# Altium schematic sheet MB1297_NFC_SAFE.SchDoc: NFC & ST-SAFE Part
size A4; DocumentNumber: MB1297; Revision: C; SheetNumber: 7; SheetTotal: 11
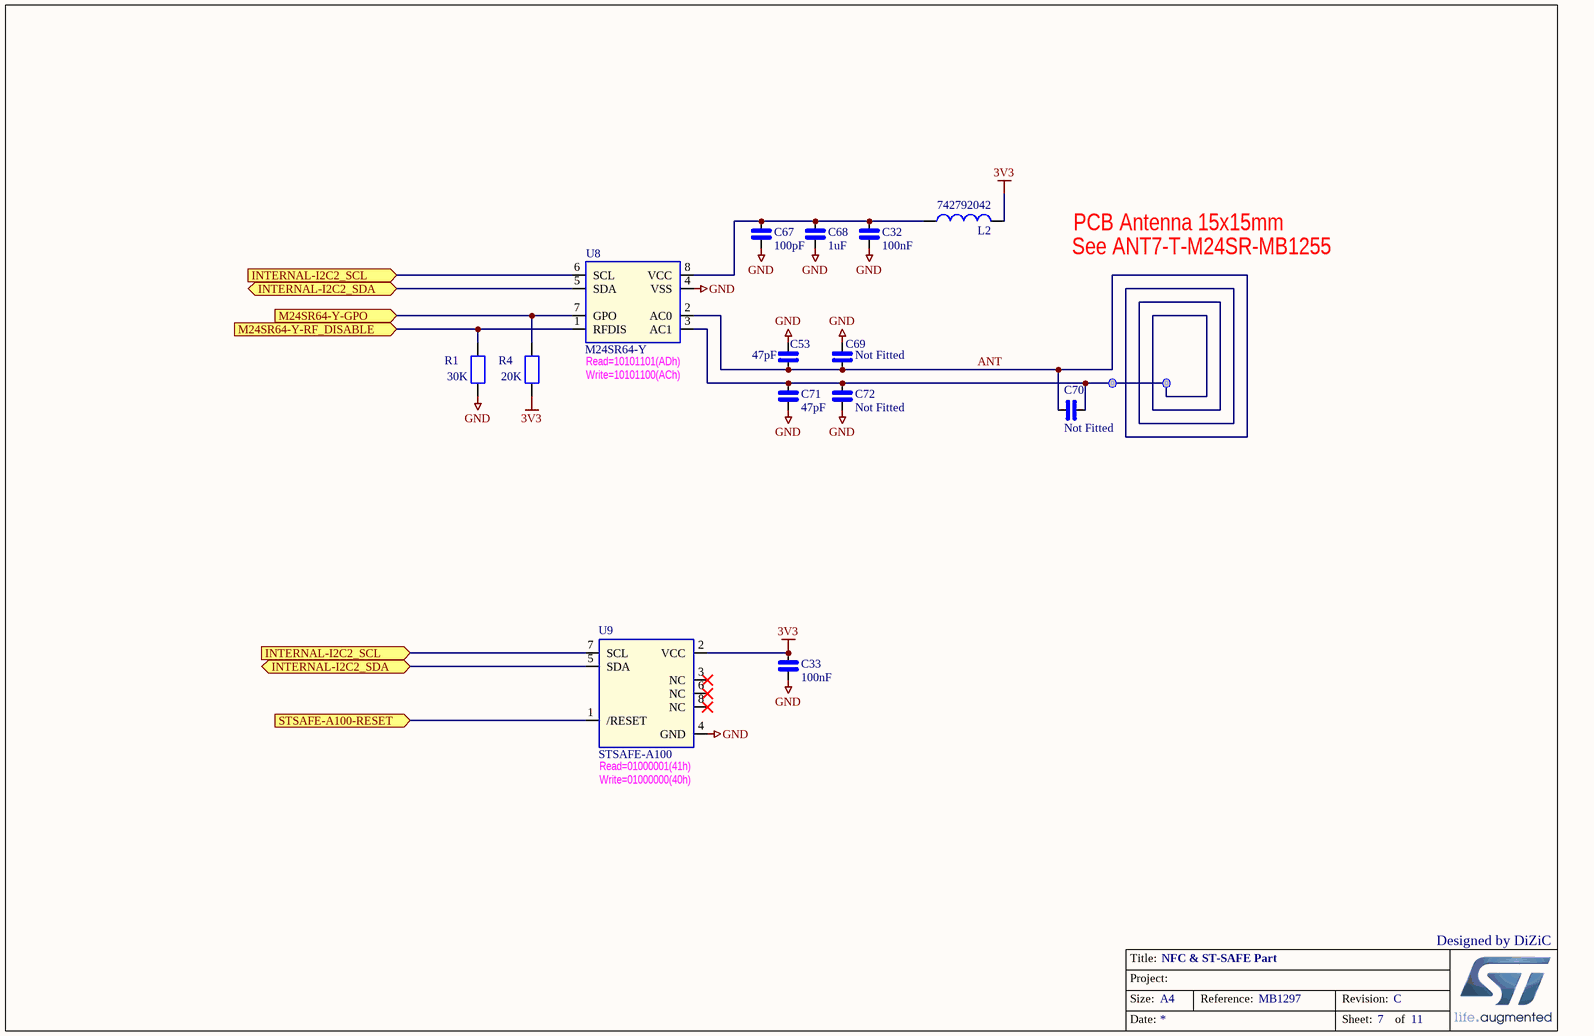
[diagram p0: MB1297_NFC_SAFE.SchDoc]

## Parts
C32  100nF  [0402_CAP_NPOL]
C33  100nF  [0402_CAP_NPOL]
C53  47pF  [0402_CAP_NPOL]
C67  100pF  [0402_CAP_NPOL]
C68  1uF  [0402_CAP_NPOL]
C69  Not Fitted  [0402_CAP_NPOL]
C70  Not Fitted  [0402_CAP_NPOL]
C71  47pF  [0402_CAP_NPOL]
C72  Not Fitted  [0402_CAP_NPOL]
L2  742792042  [0603L]
R1  30K  [0402_RES]
R4  20K  [0402_RES]
U8  M24SR64-Y  [SOP8]
U9  STSAFE-A100  [SOP8]

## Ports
INTERNAL-I2C2_SCL, INTERNAL-I2C2_SDA, M24SR64-Y-GPO, M24SR64-Y-RF_DISABLE, STSAFE-A100-RESET

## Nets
3V3: C33.1 L2.2 R4.1 U9.2(VCC)
GND: C32.2 C33.2 C53.2 C67.2 C68.2 C69.2 C71.2 C72.2 R1.1 U8.4(VSS) U9.4(GND)
ANT: C53.1 C69.1 C70.1 C70.2 C71.1 C72.1 U8.2(AC0) U8.3(AC1)
INTERNAL-I2C2_SCL: U8.6(SCL) U9.7(SCL) ; port INTERNAL-I2C2_SCL
INTERNAL-I2C2_SDA: U8.5(SDA) U9.5(SDA) ; port INTERNAL-I2C2_SDA
M24SR64-Y-GPO: R4.2 U8.7(GPO) ; port M24SR64-Y-GPO
M24SR64-Y-RF_DISABLE: R1.2 U8.1(RFDIS) ; port M24SR64-Y-RF_DISABLE
STSAFE-A100-RESET: U9.1(/RESET) ; port STSAFE-A100-RESET
NetC32_1: C32.1 C67.1 C68.1 L2.1 U8.8(VCC)

Not connected (* = marked no-connect by the designer): U9 3(NC)* 6(NC)* 8(NC)*

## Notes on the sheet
- PCB Antenna 15x15mm
- See ANT7-T-M24SR-MB1255
- (near U8) Read=10101101(ADh)
- Write=10101100(ACh)
- (near U9) Read=01000001(41h)
- (near U9) Write=01000000(40h)
- Designed by DiZiC

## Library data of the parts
C32 C33 C53 C67-C72 = CAP_NPOL: Capacitor_not polarized
L2 = Inductor: Value: 100uH
R1 R4 = RES: Resistor
U8 = M24SR64-Y: M24SR64-Y  64K_EEPROM NFC/RFID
